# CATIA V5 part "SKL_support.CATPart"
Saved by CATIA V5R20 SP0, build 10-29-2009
Part number: SKL_support
Publications: "Axe_G_support", "Axe_F_support", "Axe_A_support", "Plan_Ref", "G", "F", "A", "Plan_Sec", "Plan_Ter"
Bounding box of the stored display mesh (mm): x -5 to 5, y 0 to 24, z 0 to 5.85
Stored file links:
  C:\Users\MATT\Desktop\CATIA_Projet_IAO\CATIA FINAL\SKL_support.CATPart
  C:\Users\MATT\Desktop\CATIA_Projet_IAO\CATIA FINAL\SKL_Parametre_Projet_IAO.CATProduct
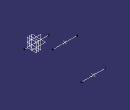
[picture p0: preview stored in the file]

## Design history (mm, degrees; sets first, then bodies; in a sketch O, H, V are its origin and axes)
Set1
  Point1 "A": (0, 0, 0), relative to Point4
  Point2 "F": (0, 0, 0), relative to Point5
  Point3 "G": (0, 0, 0), relative to Point6
  Plane1 "Plan_Ref": type Offset, RefPlane Plane4, Offset 0
  Line1 "Axe_A_support": type Normal, RefPoint Point1, RefSkin Plane1, Start -5, End 5
  Line2 "Axe_F_support": type Normal, RefPoint Point2, RefSkin Plane1, Start -5, End 5
  Line3 "Axe_G_support": type Normal, RefPoint Point3, RefSkin Plane1, Start -5, End 5
  Plane2 "Plan_Sec": type Offset, RefPlane Plane5, Offset 0
  Plane3 "Plan_Ter": type Offset, RefPlane Plane6, Offset 0
Set2
  Point4 "A": linked copy from another document
  Point5 "F": linked copy from another document
  Point6 "G": linked copy from another document
  Plane4 "Plan_Ref": linked copy from another document
  Plane5 "Plan_Sec": linked copy from another document
  Plane6 "Plan_Ter": linked copy from another document
Body1 (main body)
